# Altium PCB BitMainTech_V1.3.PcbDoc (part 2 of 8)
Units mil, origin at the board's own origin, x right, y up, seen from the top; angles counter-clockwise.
Board outline 9842.52 x 6082.68 mil, 4 copper layers (Top Layer, Mid-Layer 1, Mid-Layer 2, Bottom Layer); 987 components, 282 nets, 3694 pads, 3174 vias.
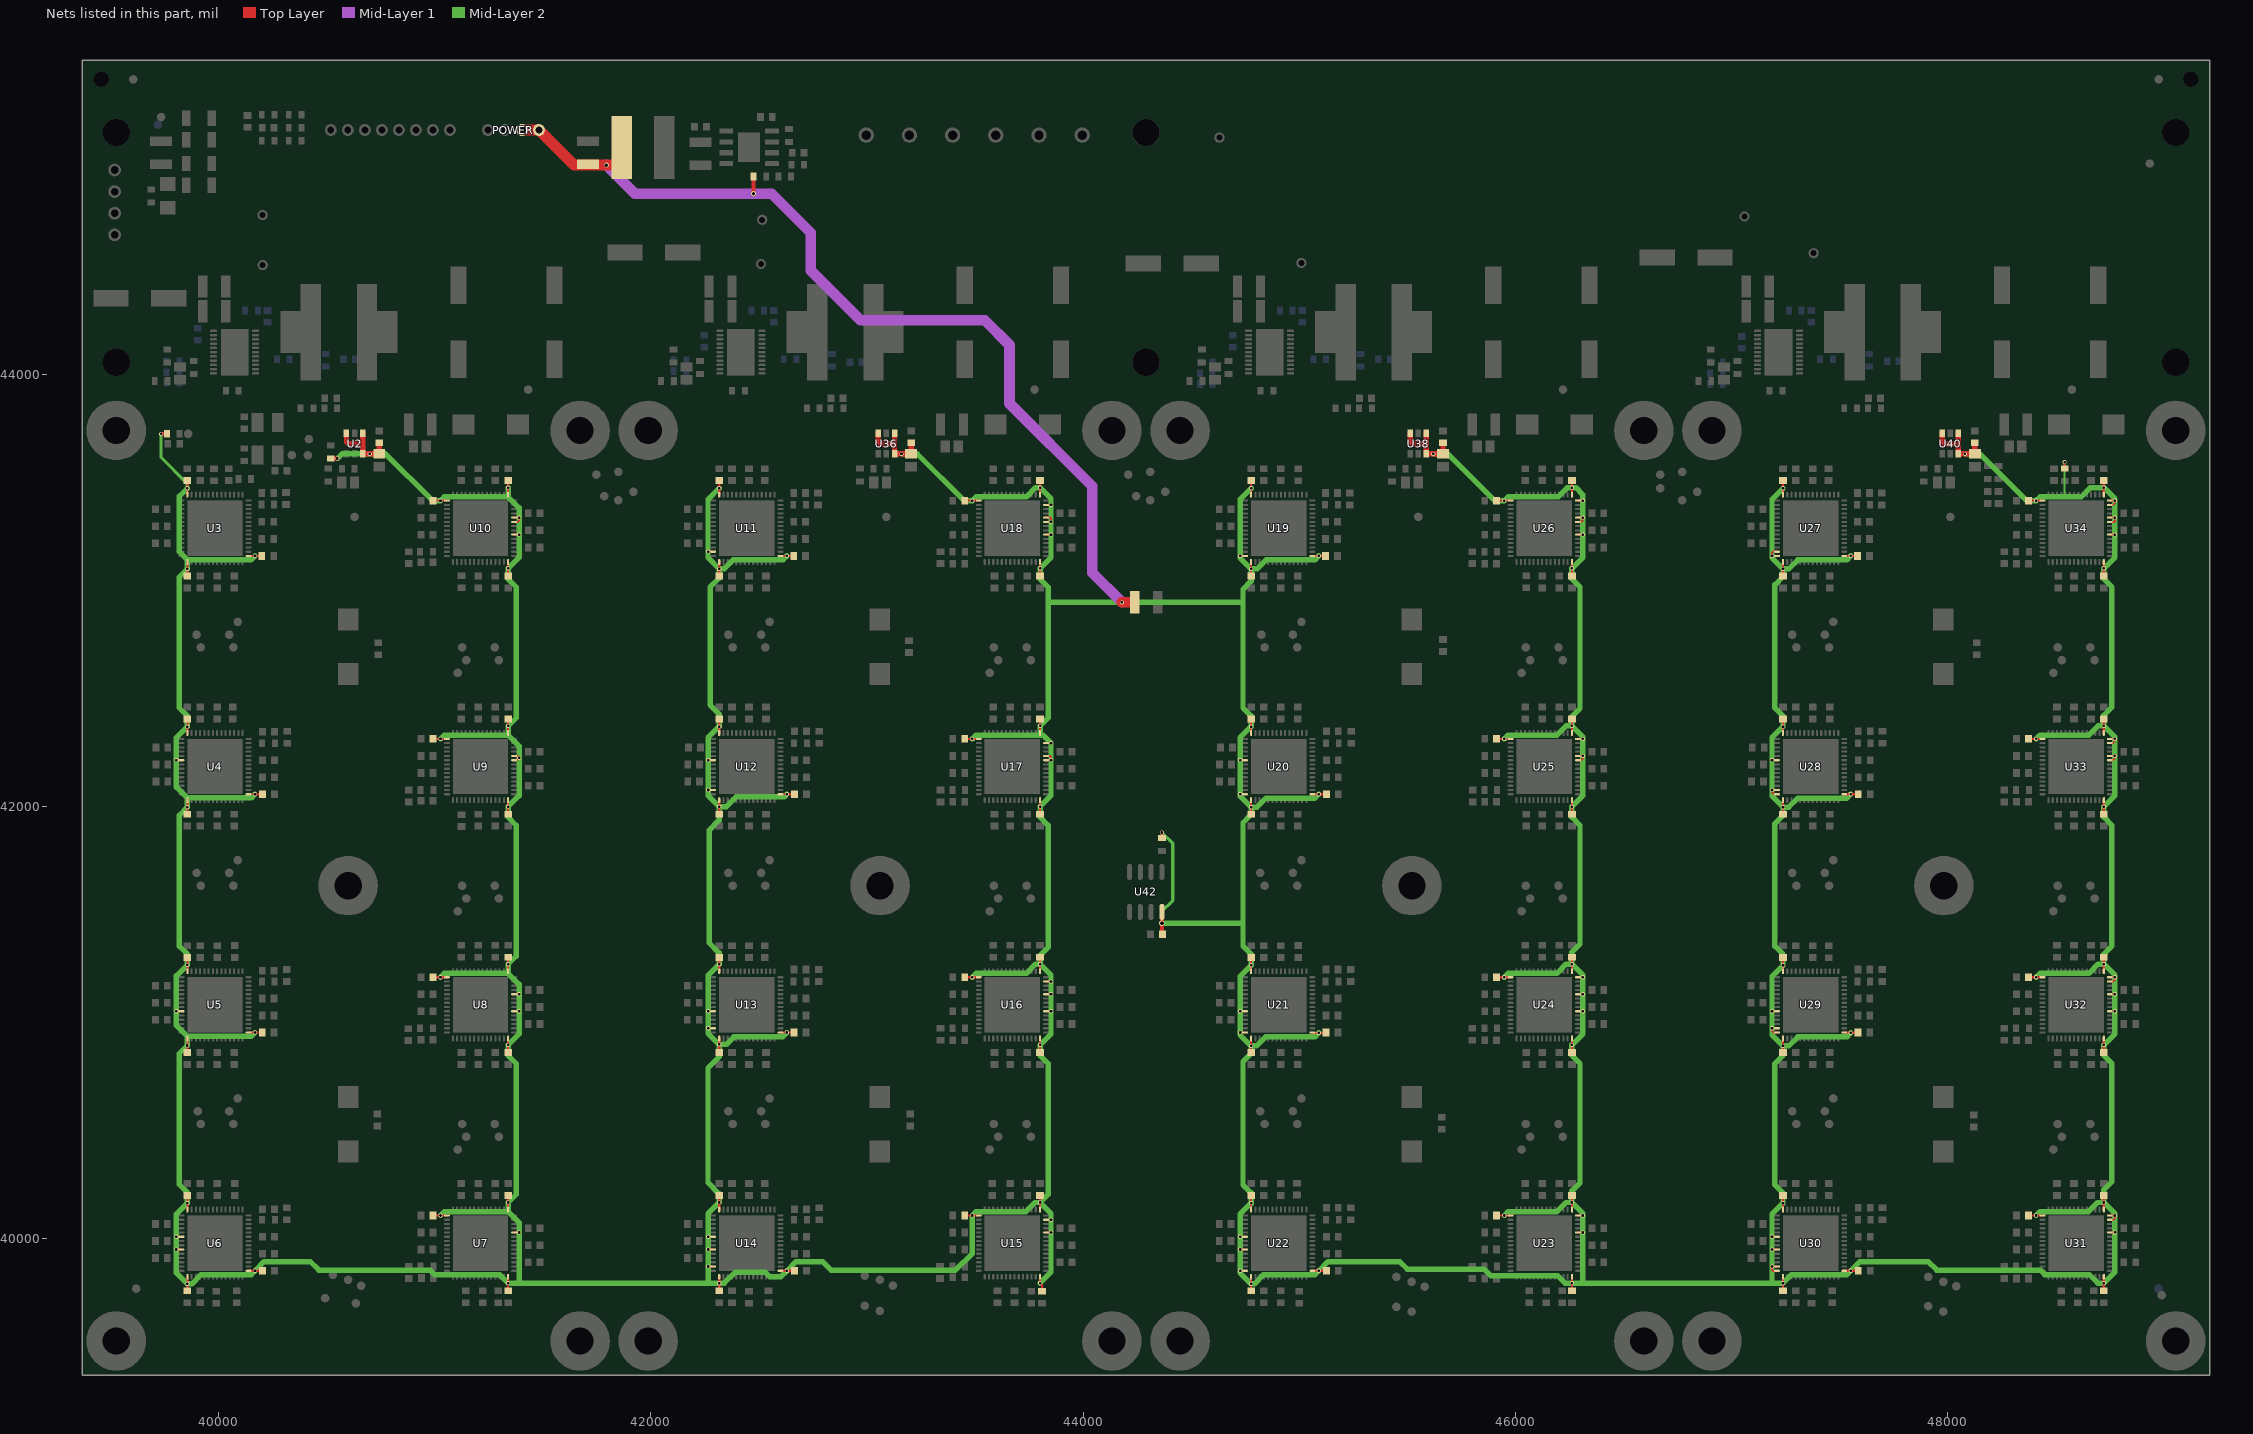
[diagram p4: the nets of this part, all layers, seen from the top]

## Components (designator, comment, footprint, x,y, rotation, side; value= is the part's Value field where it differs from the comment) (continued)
TP69 "TP" TP_SMD 44245.63,43436.63 r90 top
TP70 "TP" TP_SMD 43738.94,40531.5 r90 top
TP71 "TP" TP_SMD 43738.94,41633.86 r90 top
TP72 "TP" TP_SMD 43738.94,42736.22 r0 top
TP73 "TP" TP_SMD 44311.02,43547.99 r90 top
TP74 "TP" TP_SMD 44380.63,43456.13 r90 top
TP75 "TP" TP_SMD 43587.83,40531.5 r90 top
TP76 "TP" TP_SMD 43607.52,40472.44 r90 top
TP77 "TP" TP_SMD 43587.83,41633.86 r90 top
TP78 "TP" TP_SMD 43607.52,41574.8 r90 top
TP79 "TP" TP_SMD 43587.83,42736.22 r0 top
TP80 "TP" TP_SMD 43607.52,42677.17 r90 top
TP81 "TP" TP_SMD 44310.63,43417.13 r90 top
TP82 "TP" TP_SMD 44209.45,43536 r90 top
TP83 "TP" TP_SMD 43758.62,40472.44 r90 top
TP84 "TP" TP_SMD 43568.15,40413.39 r90 top
TP85 "TP" TP_SMD 43758.62,41574.8 r90 top
TP86 "TP" TP_SMD 43568.15,41515.75 r90 top
TP87 "TP" TP_SMD 43758.62,42677.17 r90 top
TP88 "TP" TP_SMD 43568.15,42618.11 r90 top
TP89 "TP" TP_SMD 44839.8,42736.22 r0 top
TP90 "TP" TP_SMD 44839.8,41633.86 r90 top
TP91 "TP" TP_SMD 44839.8,40531.5 r90 top
TP92 "TP" TP_SMD 45450,39685.62 r90 top
TP93 "TP" TP_SMD 44990.91,42736.22 r0 top
TP94 "TP" TP_SMD 44971.22,42795.28 r90 top
TP95 "TP" TP_SMD 44990.91,41633.86 r0 top
TP96 "TP" TP_SMD 44971.22,41692.91 r90 top
TP97 "TP" TP_SMD 44990.91,40531.5 r90 top
TP98 "TP" TP_SMD 44971.22,40590.55 r90 top
TP99 "TP" TP_SMD 45520,39801.18 r90 top
TP100 "TP" TP_SMD 45580,39778.98 r90 top
TP101 "TP" TP_SMD 44825,42795.28 r90 top
TP102 "TP" TP_SMD 45010.59,42854.33 r90 top
TP103 "TP" TP_SMD 44820.12,41692.91 r90 top
TP104 "TP" TP_SMD 45010.59,41751.97 r90 top
TP105 "TP" TP_SMD 44820.12,40590.55 r90 top
TP106 "TP" TP_SMD 45010.59,40649.61 r90 top
TP107 "TP" TP_SMD 45520,39663.82 r90 top
TP108 "TP" TP_SMD 45450,39824.23 r90 top
TP109 "TP" TP_SMD 46199.57,40531.5 r90 top
TP110 "TP" TP_SMD 46199.57,41633.86 r90 top
TP111 "TP" TP_SMD 46199.57,42736.22 r90 top
TP112 "TP" TP_SMD 46670.08,43472.81 r90 top
TP113 "TP" TP_SMD 46048.46,40531.5 r90 top
TP114 "TP" TP_SMD 46068.15,40472.44 r90 top
TP115 "TP" TP_SMD 46048.46,41633.86 r90 top
TP116 "TP" TP_SMD 46068.15,41574.8 r90 top
TP117 "TP" TP_SMD 46048.46,42736.22 r90 top
TP118 "TP" TP_SMD 46068.15,42677.17 r90 top
TP119 "TP" TP_SMD 46771.65,43547.99 r90 top
TP120 "TP" TP_SMD 46841.26,43456.13 r90 top
TP121 "TP" TP_SMD 46219.25,40472.44 r90 top
TP122 "TP" TP_SMD 46028.78,40413.39 r90 top
TP123 "TP" TP_SMD 46219.25,41574.8 r90 top
TP124 "TP" TP_SMD 46028.78,41515.75 r90 top
TP125 "TP" TP_SMD 46219.25,42677.17 r90 top
TP126 "TP" TP_SMD 46028.78,42618.11 r90 top
TP127 "TP" TP_SMD 46771.26,43417.13 r90 top
TP128 "TP" TP_SMD 46670.08,43536 r90 top
TP129 "VPLL" TP_SMD_1.0 43090.55,43340 r0 top
TP130 "TP" TP_SMD 47300.43,41633.86 r90 top
TP131 "TP" TP_SMD 47300.43,40531.5 r90 top
TP132 "TP" TP_SMD 47910,39688.82 r90 top
TP133 "TP" TP_SMD 47451.54,42736.22 r0 top
TP134 "TP" TP_SMD 47431.85,42795.28 r90 top
TP135 "TP" TP_SMD 47451.54,41633.86 r0 top
TP136 "TP" TP_SMD 47431.85,41692.91 r90 top
TP137 "TP" TP_SMD 47451.54,40531.5 r90 top
TP138 "TP" TP_SMD 47431.85,40590.55 r90 top
TP139 "TP" TP_SMD 47980,39801.18 r90 top
TP140 "TP" TP_SMD 48040,39781.18 r90 top
TP141 "TP" TP_SMD 47280.75,42795.28 r90 top
TP142 "TP" TP_SMD 47471.22,42854.33 r90 top
TP143 "TP" TP_SMD 47280.75,41692.91 r90 top
TP144 "TP" TP_SMD 47471.22,41751.97 r90 top
TP145 "TP" TP_SMD 47280.75,40590.55 r90 top
TP146 "TP" TP_SMD 47471.22,40649.61 r90 top
TP147 "TP" TP_SMD 47980,39663.82 r90 top
TP148 "TP" TP_SMD 47910,39824.23 r90 top
TP149 "TP" TP_SMD 48660.2,40531.5 r90 top
TP150 "TP" TP_SMD 48660.2,41633.86 r90 top
TP151 "TP" TP_SMD 48660.2,42736.22 r90 top
TP152 "TP" TP_SMD 48509.09,40531.5 r90 top
TP153 "TP" TP_SMD 48528.78,40472.44 r90 top
TP154 "TP" TP_SMD 48509.09,41633.86 r90 top
TP155 "TP" TP_SMD 48528.78,41574.8 r90 top
TP156 "TP" TP_SMD 48509.09,42736.22 r90 top
TP157 "TP" TP_SMD 48528.78,42677.17 r90 top
TP158 "TP" TP_SMD 48679.88,40472.44 r90 top
TP159 "TP" TP_SMD 48489.41,40413.39 r90 top
TP160 "TP" TP_SMD 48679.88,41574.8 r90 top
TP161 "TP" TP_SMD 48489.41,41515.75 r90 top
TP162 "TP" TP_SMD 48679.88,42677.17 r90 top
TP163 "TP" TP_SMD 48489.41,42618.11 r90 top
TP164 "VOUT" TP_SMD_1.0 43775.59,43929.13 r0 top
TP165 "+12V" TP 42515.75,44714.57 r0 top
TP166 "GND" TP 42510,44510 r0 top
TP167 "VPLL" TP_SMD_1.0 40629.92,43340 r90 top
TP168 "VOUT" TP_SMD_1.0 46220.47,43929.13 r0 top
TP169 "+12V" TP 44630.91,45094.49 r0 top
TP170 "GND" TP 45010,44515 r0 top
TP171 "VPLL" TP_SMD_1.0 45551.18,43340 r0 top
TP172 "VOUT" TP_SMD_1.0 48574.8,43929.13 r0 top
TP173 "+12V" TP 47060,44730 r0 top
TP174 "GND" TP 47380,44560 r0 top
TP175 "VPLL" TP_SMD_1.0 48011.81,43340 r0 top
U1 "TPS53355DQPR" TPS53355 40171.26,44003.94 r180 top locked
U2 "RT9041B-10GE" SOT23-6_L 40629.92,43679.13 r270 top
U3 "BM1380" QFN56 39984.25,43287.4 r270 top locked
U4 "BM1380" QFN56 39984.25,42185.04 r270 top locked
U5 "BM1380" QFN56 39984.25,41082.68 r270 top locked
U6 "BM1380" QFN56 39984.25,39980.32 r270 top locked
U7 "BM1380" QFN56 41212.6,39980.32 r90 top locked
U8 "BM1380" QFN56 41212.6,41082.68 r90 top locked
U9 "BM1380" QFN56 41212.6,42185.04 r90 top locked
U10 "BM1380" QFN56 41212.6,43287.4 r90 top locked
U11 "BM1380" QFN56 42444.88,43287.4 r270 top locked
U12 "BM1380" QFN56 42444.88,42185.04 r270 top locked
U13 "BM1380" QFN56 42444.88,41082.68 r270 top
U14 "BM1380" QFN56 42444.88,39980.31 r270 top locked
U15 "BM1380" QFN56 43673.23,39980.32 r90 top locked
U16 "BM1380" QFN56 43673.23,41082.68 r90 top locked
U17 "BM1380" QFN56 43673.23,42185.04 r90 top locked
U18 "BM1380" QFN56 43673.23,43287.4 r90 top locked
U19 "BM1380" QFN56 44905.51,43287.4 r270 top locked
U20 "BM1380" QFN56 44905.51,42185.04 r270 top locked
U21 "BM1380" QFN56 44905.51,41082.68 r270 top locked
U22 "BM1380" QFN56 44905.51,39980.32 r270 top locked
U23 "BM1380" QFN56 46133.86,39980.32 r90 top locked
U24 "BM1380" QFN56 46133.86,41082.68 r90 top locked
U25 "BM1380" QFN56 46133.86,42185.04 r90 top locked
U26 "BM1380" QFN56 46133.86,43287.4 r90 top locked
U27 "BM1380" QFN56 47366.14,43287.4 r270 top locked
U28 "BM1380" QFN56 47366.14,42185.04 r270 top locked
U29 "BM1380" QFN56 47366.14,41082.68 r270 top locked
U30 "BM1380" QFN56 47366.14,39980.32 r270 top locked
U31 "BM1380" QFN56 48594.49,39980.32 r90 top locked
U32 "BM1380" QFN56 48594.49,41082.68 r90 top locked
U33 "BM1380" QFN56 48594.49,42185.04 r90 top locked
U34 "BM1380" QFN56 48594.49,43287.4 r90 top locked
U35 "MP1484" SOIC8L 42455,45050 r270 top
U36 "RT9041B-10GE" SOT23-6_L 43090.55,43679.13 r270 top
U37 "TPS53355DQPR" TPS53355 44959.45,44003.94 r180 top
U38 "RT9041B-10GE" SOT23-6_L 45551.18,43679.13 r270 top
U39 "TPS53355DQPR" TPS53355 47313.78,44003.94 r180 top
U40 "RT9041B-10GE" SOT23-6_L 48011.81,43679.13 r270 top
U41 "TPS53355DQPR" TPS53355 42513.78,44003.94 r180 top
U42 "LM75A" SO8_L 44290,41605 r270 top locked
Y1 "25MHz" SMX2 40228.35,43702.76 r90 top
? "ANT_Logo" ANT_Logo_930x370 48085,44935 r0 top

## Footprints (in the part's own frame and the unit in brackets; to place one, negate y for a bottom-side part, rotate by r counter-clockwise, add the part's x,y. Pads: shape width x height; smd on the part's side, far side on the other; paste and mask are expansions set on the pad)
4Pin_180 [mm]
  round 1.4 hole 0.8: 1(-3,0) 2(-1,0) 3(1,0) 4(3,0)
  silkscreen extent -4.8,-2.5 4.8,2.9
4PINFAN [mm]
  round 1.5 hole 0.9 paste+0.05 mask+0.05: 1(3.81,0) 2(1.27,0) 3(-1.27,0) 4(-3.81,0)
  silkscreen extent -5.03,-2.85 5,2.85
8Pin_180 [mm]
  round 1.4 hole 0.8: 1(-7,0) 2(-5,0) 3(-3,0) 4(-1,0) 5(1,0) 6(3,0) 7(5,0) 8(7,0)
  silkscreen extent -8.8,-2.5 8.8,2.9
ANT_Logo_930x370 [mil]
  silkscreen extent -435,-69 481,283
CAP1210(3225)_TAN [mm] "Chip Capacitor, Body 3.2x2.5mm, IPC High Density"
  rect 1.1x2.6 smd: 1(-1.35,0) 2(1.35,0)
  silkscreen extent -0.4,-1.2 0.42,1.2, body extent -1.7,-1.35 1.7,1.35, height 1.35
CAPC2012L [mm] "Chip Capacitor, Body 2.0x1.3mm, IPC High Density"
  rect 1.1x1.4 smd: 1(-0.75,0) 2(0.75,0)
  silkscreen extent -1.6,-0.6 -1.6,0.6, body extent -1.1,-0.72 1.1,0.72, height 1.1
CAPC3225L [mm] "Chip Capacitor, Body 3.2x2.5mm, IPC High Density"
  rect 1.1x2.6 smd: 1(1.35,0) 2(-1.35,0)
  silkscreen extent -0.4,-1.2 0.4,1.2, body extent -1.7,-1.35 1.7,1.35, height 1.35
CC0603(1608) [mm] "Chip Capacitor, Body 1.6x0.8mm, IPC High Density"
  rect 0.8x0.9 smd: 1(-0.7,0) 2(0.7,0)
  silkscreen extent -1.4,-0.35 -1.4,0.35, body extent -0.87,-0.48 0.87,0.47, height 0.85
CC0805(2012) [mm] "Chip Capacitor, Body 2.0x1.3mm, IPC High Density"
  rect 1.1x1.4 smd: 1(-0.75,0) 2(0.75,0)
  silkscreen extent -1.6,-0.6 -1.6,0.6, body extent -1.1,-0.73 1.1,0.72, height 1.1
CC1210(3225) [mm] "Chip Capacitor, Body 3.2x2.5mm, IPC High Density"
  rect 1.1x2.6 smd: 1(1.35,0) 2(-1.35,0)
  silkscreen extent -0.4,-1.2 0.42,1.2, body extent -1.7,-1.35 1.7,1.35, height 1.35
CD3216-1206 [mm] "Chip Diode; Body 3.2 x 1.6 mm (LxW typ)"
  rect 1.6x1.8 smd: 1(-1.4,0) 2(1.4,0)
  silkscreen extent -0.3,-0.8 0.3,0.8
D [mm] "Capacitor, SM Tantalum; Body 7.3 x 4.3 mm (LxW typ)"
  rect 2.6x2.4 smd: 1(-3.2,0) 2(3.2,0)
  silkscreen extent -4.57,-2.3 3.8,2.42
E12 [mm] "SVP"
  rect 1.9x4.15 smd: 1(0,-3.4) 2(0,3.4)
  silkscreen extent -4.31,-5.71 4.2,5.71, body extent -3.98,-3.99 4,3.99, height 12.8
F12 [mm] "SVP"
  rect 1.9x4.4 smd: 1(0,-4.35) 2(0,4.35)
  silkscreen extent -5.2,-6.84 5.2,6.85, body extent -5,-5.29 5.01,5.28, height 13.4
FB0603(1608) [mm] "Ferrite Bead"
  rect 0.7x0.9 smd: 1(0,0) 2(1.5,0)
  silkscreen extent 0.55,-0.35 0.95,0.35, body extent -0.1,-0.48 1.6,0.47, height 0.6
HOLE_3.2#1 [mm]
  round 3.2 hole 3.2 unplated: 0(0,10)
HOLE_3.2#2 [mm]
  round 3.2 hole 3.2 unplated: 0(0,0)
IHLP5050 [mm]
  rect 2.945x4.95 smd: 1(-5.407,0) 2(5.407,0)
  rect 2.388x11.328 smd: 1(-3.28,0) 2(3.32,-0.03)
  silkscreen extent -7.14,-6.45 7.14,6.45, body extent -6.6,-6.45 6.6,6.45, height 6.5
INDC3216L [mm] "Chip Inductor, Body 3.2x1.6mm, IPC High Density"
  rect 1x1.8 smd: 1(-1.5,0) 2(1.5,0)
  silkscreen extent -0.6,-0.8 0.6,0.8, body extent -1.75,-0.95 1.75,0.95, height 1.9
LED0603(1608) [mm] "Chip LED, Body 1.6x0.8mm, IPC High Density"
  rect 0.8x0.9 smd: 1(0.7,0) 2(-0.7,0)
  silkscreen extent -1.4,-0.35 -1.4,0.35, body extent -0.87,-0.48 0.87,0.47, height 0.85
MASK [mm] "SMD MASK 1mm"
  round 1 smd: 0(0,0)
  Top Layer circle w0.254: c0,0 r1
MHOLE2 [mm]
  round 7 hole 3.2 unplated: 0(0,0)
QFN56 [mm]
  oval 0.7x0.25 smd: 1(-3.95,3.25) 2(-3.95,2.75) 3(-3.95,2.25) 4(-3.95,1.75) 5(-3.95,1.25) 6(-3.95,0.75) 7(-3.95,0.25) 8(-3.95,-0.25) 9(-3.95,-0.75) 10(-3.95,-1.25) 11(-3.95,-1.75) 12(-3.95,-2.25) 13(-3.95,-2.75) 14(-3.95,-3.25) 29(3.95,-3.25) 30(3.95,-2.75) 31(3.95,-2.25) 32(3.95,-1.75) 33(3.95,-1.25) 34(3.95,-0.75) 35(3.95,-0.25) 36(3.95,0.25) 37(3.95,0.75) 38(3.95,1.25) 39(3.95,1.75) 40(3.95,2.25) 41(3.95,2.75) 42(3.95,3.25)
  oval 0.25x0.7 smd: 15(-3.25,-3.95) 16(-2.75,-3.95) 17(-2.25,-3.95) 18(-1.75,-3.95) 19(-1.25,-3.95) 20(-0.75,-3.95) 21(-0.25,-3.95) 22(0.25,-3.95) 23(0.75,-3.95) 24(1.25,-3.95) 25(1.75,-3.95) 26(2.25,-3.95) 27(2.75,-3.95) 28(3.25,-3.95) 43(3.25,3.95) 44(2.75,3.95) 45(2.25,3.95) 46(1.75,3.95) 47(1.25,3.95) 48(0.75,3.95) 49(0.25,3.95) 50(-0.25,3.95) 51(-0.75,3.95) 52(-1.25,3.95) 53(-1.75,3.95) 54(-2.25,3.95) 55(-2.75,3.95) 56(-3.25,3.95)
  rect 6.5x6.5 smd: 57(0,0)
  rect 6.5x6.5 smd far side: 57(0,0)
  silkscreen extent -4.9,-4.23 4.23,4.23, body extent -4.08,-4.08 4.08,4.08, height 0.9
RR0603(1608) [mm] "Chip Resistor, Body 1.6x0.8mm, IPC High Density"
  rect 0.7x0.9 smd: 1(-0.75,0) 2(0.75,0)
  silkscreen extent -0.2,-0.35 0.2,0.35, body extent -0.85,-0.48 0.85,0.47, height 0.6
SMD_L_7.4x7.4 [mm]
  rect 2.4x7.4 smd: 1(-2.5,0) 2(2.5,0)
  silkscreen extent -3.8,-4 3.8,4
SMX2 [mm]
  rect 2.2x1.4 smd: 1(-1.925,-1.175) 2(1.875,-1.175) 3(1.875,1.225) 4(-1.925,1.225)
  silkscreen extent -2.99,-2.51 2.47,1.68
SO8_L [mm] "SOIC, 8-Leads, Body 4.9x3.9mm, Pitch 1.27mm, IPC High Density"
  oval 1.9x0.6 smd: 1(-2.35,1.905) 2(-2.35,0.635) 3(-2.35,-0.635) 4(-2.35,-1.905) 5(2.35,-1.905) 6(2.35,-0.635) 7(2.35,0.635) 8(2.35,1.905)
  silkscreen extent -2.47,-2.5 1,2.88, body extent -2,-2.5 2,2.5, height 1.75
SOIC8L [mm]
  rect 3.51x2.62 smd: 0(0,0)
  rect 0.61x1.6 smd: 1(-1.905,-2.7) 2(-0.635,-2.7) 3(0.635,-2.7) 4(1.905,-2.7) 5(1.905,2.7) 6(0.635,2.7) 7(-0.635,2.7) 8(-1.905,2.7)
  silkscreen extent -2.4,-2 2.4,2
SOT23-6_L [mm] "SOT23, 6-Leads, Body 2.9x1.6mm, Pitch 0.95mm, Lead Span 2.7mm, IPC High Density"
  rect 0.9x0.65 smd: 1(-1.2,0.95) 2(-1.2,0) 3(-1.2,-0.95) 4(1.2,-0.95) 5(1.2,0) 6(1.2,0.95)
  silkscreen extent -1.32,-1.55 0.35,1.95, body extent -0.9,-1.55 0.9,1.55, height 1.45
TERMINAL_3 [mm]
  round 1.8 hole 1.1: 1(0,0) 2(5.08,0) 3(10.16,0)
  silkscreen extent -2.54,-3.81 12.7,3.81
TP [mm]
  round 1.2 hole 0.7: 1(0,0)
  silkscreen extent -1.27,-1.27 1.27,1.27
TP_SMD [mm]
  round 1 smd: 1(0,0)
TP_SMD_1.0 [mm]
  round 1 smd: 1(0,0)
  silkscreen extent -1,-1 1,1
TPS53355 [mm]
  oval 0.85x0.28 smd: 1(-0.02,0) 2(-0.02,-0.5) 3(-0.02,-1) 4(-0.02,-1.5) 5(-0.02,-2) 6(-0.02,-2.5) 7(-0.02,-3) 8(-0.02,-3.5) 9(-0.02,-4) 10(-0.02,-4.5) 11(-0.02,-5) 12(4.92,-5) 13(4.92,-4.5) 14(4.92,-4) 15(4.92,-3.5) 16(4.92,-3) 17(4.92,-2.5) 18(4.92,-2) 19(4.92,-1.5) 20(4.92,-1) 21(4.92,-0.5) 22(4.92,0)
  rect 3.24x5.48 smd: PG(2.45,-2.5)
  rect 3.24x5.48 smd far side: PG(2.45,-2.5)
  silkscreen extent -0.8,-5.55 5,0.55

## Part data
C1 C5 C6 C7 C10 C11 C12 C13 C21 C22 C23 C24 C25 C26 C27 C28 C29 C30 C31 C32 C33 C34 C35 C36 C37 C38 C39 C40 C41 C42 C43 C44 C45 C46 C47 C48 C49 C50 C51 C52 C53 C54 C55 C56 C57 C58 C59 C60 C61 C62 C63 C64 C65 C66 C67 C68 C69 C70 C71 C72 C73 C74 C75 C76 C77 C78 C79 C80 C81 C82 C83 C84 C85 C86 C87 C88 C89 C90 C91 C92 C93 C94 C95 C96 C97 C98 C99 C100 C101 C102 C103 C104 C105 C106 C107 C108 C109 C110 C111 C112 C113 C114 C115 C116 C117 C118 C119 C120 C121 C122 C123 C124 C125 C126 C127 C128 C129 C130 C131 C132 C133 C134 C135 C136 C137 C138 C139 C140 C141 C142 C143 C144 C145 C146 C147 C148 C149 C150 C151 C156 C157 C158 C159 C160 C161 C162 C163 C164 C165 C166 C167 C168 C169 C170 C171 C172 C173 C174 C175 C176 C177 C178 C179 C180 C181 C182 C183 C184 C185 C186 C187 C188 C189 C190 C191 C192 C193 C194 C195 C196 C197 C198 C199 C200 C201 C202 C203 C204 C205 C206 C207 C208 C209 C210 C211 C212 C213 C214 C215 C216 C217 C218 C219 C220 C221 C222 C223 C224 C225 C226 C227 C228 C229 C230 C231 C232 C233 C234 C235 C236 C237 C238 C239 C240 C241 C242 C243 C244 C245 C246 C247 C248 C249 C250 C251 C252 C253 C254 C255 C256 C257 C258 C259 C260 C261 C262 C263 C264 C265 C266 C267 C268 C269 C270 C271 C272 C273 C274 C275 C276 C277 C278 C279 C280 C281 C282 C283 C288 C289 C290 C291 C292 C293 C294 C295 C296 C297 C298 C299 C300 C301 C302 C303 C304 C305 C306 C307 C308 C309 C310 C311 C312 C313 C314 C315 C316 C317 C318 C319 C320 C321 C322 C323 C324 C325 C326 C327 C328 C329 C330 C331 C332 C333 C334 C335 C336 C337 C338 C339 C340 C341 C342 C343 C344 C345 C346 C347 C348 C349 C350 C351 C352 C353 C354 C355 C356 C357 C358 C359 C360 C361 C362 C363 C364 C365 C366 C367 C368 C369 C370 C371 C372 C373 C374 C375 C376 C377 C378 C379 C380 C381 C382 C383 C384 C385 C386 C387 C388 C389 C390 C391 C392 C393 C394 C395 C396 C397 C398 C399 C400 C401 C402 C403 C404 C405 C406 C407 C408 C409 C410 C411 C412 C413 C414 C415 C420 C421 C422 C423 C424 C425 C426 C427 C428 C429 C430 C431 C432 C433 C434 C435 C436 C437 C438 C439 C440 C441 C442 C443 C444 C445 C446 C447 C448 C449 C450 C451 C452 C453 C454 C455 C456 C457 C458 C459 C460 C461 C462 C463 C464 C465 C466 C467 C468 C469 C470 C471 C472 C473 C474 C475 C476 C477 C478 C479 C480 C481 C482 C483 C484 C485 C486 C487 C488 C489 C490 C491 C492 C493 C494 C495 C496 C497 C498 C499 C500 C501 C502 C503 C504 C505 C506 C507 C508 C509 C510 C511 C512 C513 C514 C515 C516 C517 C518 C519 C520 C521 C522 C523 C524 C525 C526 C527 C528 C529 C530 C531 C532 C533 C534 C535 C536 C537 C538 C539 C540 C541 C542 C543 C544 C545 C546 C547 C553 C554 C557 C558 C559 C560 C564 C568 C569 C570 C573 C574 C575 C576 C580 C584 C585 C586 C589 C590 C591 C592 C598 C600: library part Cap, "Capacitor"
C2 C3 C565 C566 C581 C582 C596 C597 C606 C607 C608 C609: library part "Cap Pol2", "Polarized Capacitor (SMD)"
C4 C567 C583 C599: library part "Cap Pol3", "Polarized Capacitor (Surface Mount)"
C8 C9 C14 C15 C16 C19 C20 C154 C155 C286 C287 C418 C419 C548 C549 C550 C551 C552 C555 C556 C561 C562 C563 C571 C572 C577 C578 C579 C587 C588 C593 C594 C595 C601 C602 C603 C604 C605: library part "Cap Semi", "Capacitor (Semiconductor SIM Model)"
C17 C18 C152 C153 C284 C285 C416 C417: library part T492C, "Solid Tantalum Chip Capacitor, T492 Series - CWR11 Style Per Mil-PRF-55365/8"
D1: "High Conductance Fast Diode"
FAN1 POWER: "Header, 4-Pin"
FB1 FB2 FB3 FB4 FB5 FB6 FB7 FB8 FB9 FB10 FB11 FB12 FB13 FB14 FB15 FB16 FB17 FB18 FB19 FB20 FB21 FB22 FB23 FB24 FB25 FB26 FB27 FB28 FB29 FB30 FB31 FB32: library part FB, "Inductor"
FB33 FB34 FB35 FB36: library part Res3, "Resistor"
J1: library part "Header 8", "Header, 8-Pin"
L1 L2 L3 L4 L5: library part Inductor, "Inductor"
M1 M2 M3 M4 M5 M6 M7 M8 M9 M10 M11 M12 M13 M14 M15 M16 M17 M18 M19 M20 M21 M22 M23 M27 M28 M32: library part M_Hole
P1 P2: library part "Header 3", "Header, 3-Pin"
R1 R2 R3 R4 R5 R6 R7 R8 R9 R10 R11 R12 R13 R14 R15 R16 R17 R18 R19 R20 R21 R22 R23 R24 R25 R26 R27 R28 R29 R30 R31 R32 R33 R34 R35 R36 R37 R38 R39 R40 R41 R42 R43 R44 R45 R46 R47 R48 R49 R50 R51 R52 R53 R54 R55 R56 R57 R58 R59 R60 R61 R62 R63 R64 R65 R66 R67 R68 R69 R70 R71 R72 R73 R74: library part Res1, "Resistor"
RF TF: library part LED0, "Typical INFRARED GaAs LED"
TP1 TP129 TP164 TP167 TP168 TP171 TP172 TP175: library part TP, "Test Point"
TP2 TP3 TP165 TP166 TP169 TP170 TP173 TP174: library part TP
TP4 TP5 TP6 TP7 TP8 TP9 TP10 TP11 TP12 TP13 TP14 TP15 TP16 TP17 TP18 TP19 TP20 TP21 TP22 TP23 TP24 TP25 TP26 TP27 TP28 TP29 TP30 TP31 TP32 TP33 TP34 TP35 TP36 TP37 TP38 TP39 TP40 TP41 TP42 TP43 TP44 TP45 TP46 TP47 TP48 TP49 TP50 TP51 TP52 TP53 TP54 TP55 TP56 TP57 TP58 TP59 TP60 TP61 TP62 TP63 TP64 TP65 TP66 TP67 TP68 TP69 TP70 TP71 TP72 TP73 TP74 TP75 TP76 TP77 TP78 TP79 TP80 TP81 TP82 TP83 TP84 TP85 TP86 TP87 TP88 TP89 TP90 TP91 TP92 TP93 TP94 TP95 TP96 TP97 TP98 TP99 TP100 TP101 TP102 TP103 TP104 TP105 TP106 TP107 TP108 TP109 TP110 TP111 TP112 TP113 TP114 TP115 TP116 TP117 TP118 TP119 TP120 TP121 TP122 TP123 TP124 TP125 TP126 TP127 TP128 TP130 TP131 TP132 TP133 TP134 TP135 TP136 TP137 TP138 TP139 TP140 TP141 TP142 TP143 TP144 TP145 TP146 TP147 TP148 TP149 TP150 TP151 TP152 TP153 TP154 TP155 TP156 TP157 TP158 TP159 TP160 TP161 TP162 TP163: "Test Point"
U1: library part TPS53355, "TI DC-DC,Output 30A."
U37 U39 U41: library part TPS53355
U42: "NXP Digital temperature sensor and thermal watchdog"
Y1: library part XTAL, "Crystal Oscillator"

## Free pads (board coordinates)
  round 70.87 hole 70.87 unplated: ""(39458.66,45364.17) ""(49124.02,45364.17)

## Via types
v1: diameter 19, hole 12, Top Layer to Bottom Layer, 1347 vias
v2: diameter 25.98, hole 12.99, Top Layer to Bottom Layer, 800 vias
v3: diameter 24, hole 16, Top Layer to Bottom Layer, 778 vias
v4: diameter 50, hole 28, Top Layer to Bottom Layer, 160 vias
v5: diameter 19.68, hole 11.81, Top Layer to Bottom Layer, 84 vias
v6: diameter 26, hole 18, Top Layer to Bottom Layer, 5 vias

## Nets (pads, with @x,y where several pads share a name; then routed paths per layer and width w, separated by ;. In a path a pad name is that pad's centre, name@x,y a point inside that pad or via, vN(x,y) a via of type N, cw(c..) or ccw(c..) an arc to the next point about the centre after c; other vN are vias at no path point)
+3.3V: C14.2 C15.2 C32.2 C33.2 C34.2 C35.2 C36.2 C37.2 C38.2 C39.2 C40.2 C41.2 C42.2 C43.2 C96.2 C97.2 C98.2 C99.2 C100.2 C101.2 C102.2 C103.2 C104.2 C105.2 C106.2 C107.2 C164.2 C165.2 C166.2 C167.2 C168.2 C169.2 C170.2 C171.2 C172.2 C173.2 C174.2 C175.2 C228.2 C229.2 C230.2 C231.2 C232.2 C233.2 C234.2 C235.2 C236.2 C237.2 C238.2 C239.2 C296.2 C297.2 C298.2 C299.2 C300.2 C301.2 C302.2 C303.2 C304.2 C305.2 C306.2 C307.2 C360.2 C361.2 C362.2 C363.2 C364.2 C365.2 C366.2 C367.2 C368.2 C369.2 C370.2 C371.2 C428.2 C429.2 C430.2 C431.2 C432.2 C433.2 C434.2 C435.2 C436.2 C437.2 C438.2 C439.2 C492.2 C493.2 C494.2 C495.2 C496.2 C497.2 C498.2 C499.2 C500.2 C501.2 C502.2 C503.2 C550.2 C561.2 C562.2 C577.2 C578.2 C593.2 C594.2 C601.1 C602.2 L5.2 POWER.3 POWER.4 R15.1 R18.2 R21.2 R71.1 R74.2 U2.1 U2.3 U2.6 U3.14 U3.29 U3.43 U4.14 U4.20 U4.29 U4.43 U5.14 U5.23 U5.29 U5.43 U6.14 U6.20 U6.23 U6.29 U6.43 U7.14 U7.24 U7.29 U7.43 U8.14 U8.20 U8.24 U8.29 U8.43 U9.14 U9.23 U9.24 U9.29 U9.43 U10.14 U10.20 U10.23 U10.24 U10.29 U10.43 U11.14 U11.27 U11.29 U11.43 U12.14 U12.20 U12.27 U12.29 U12.43 U13.14 U13.23 U13.27 U13.29 U13.43 U14.14 U14.20 U14.23 U14.27 U14.29 U14.43 U15.14 U15.24 U15.27 U15.29 U15.43 U16.14 U16.20 U16.24 U16.27 U16.29 U16.43 U17.14 U17.23 U17.24 U17.27 U17.29 U17.43 U18.14 U18.20 U18.23 U18.24 U18.27 U18.29 U18.43 U19.14 U19.28 U19.29 U19.43 U20.14 U20.20 U20.28 U20.29 U20.43 U21.14 U21.23 U21.28 U21.29 U21.43 U22.14 U22.20 U22.23 U22.28 U22.29 U22.43 U23.14 U23.24 U23.28 U23.29 U23.43 U24.14 U24.20 U24.24 U24.28 U24.29 U24.43 U25.14 U25.23 U25.24 U25.28 U25.29 U25.43 U26.14 U26.20 U26.23 U26.24 U26.28 U26.29 U26.43 U27.14 U27.27 U27.28 U27.29 U27.43 U28.14 U28.20 U28.27 U28.28 U28.29 U28.43 U29.14 U29.23 U29.27 U29.28 U29.29 U29.43 U30.14 U30.20 U30.23 U30.27 U30.28 U30.29 U30.43 U31.14 U31.24 U31.27 U31.28 U31.29 U31.43 U32.14 U32.20 U32.24 U32.27 U32.28 U32.29 U32.43 U33.14 U33.23 U33.24 U33.27 U33.28 U33.29 U33.43 U34.14 U34.20 U34.23 U34.24 U34.27 U34.28 U34.29 U34.43 U36.1 U36.3 U36.6 U38.1 U38.3 U38.6 U40.1 U40.3 U40.6 U42.8 | length 67165
  Top Layer w8: v1(43801.18,39795.28) 43810,39786.46 C168.2@43810,39757.56
  Top Layer w9: v1(39805.43,39950.79) U6.23@39828.74,39950.79 ; v1(39805.43,40009.84) U6.20@39828.74,40009.84 ; v1(39805.43,41053.15) U5.23@39828.74,41053.15 ; v1(39805.43,42214.57) U4.20@39828.74,42214.57 ; U5.43@40139.76,40954.72 v1(40169.29,40954.72) ; U4.43@40139.76,42057.09 v1(40169.29,42057.09) ; U3.43@40139.76,43159.45 v1(40169.29,43159.45) ; U7.24@41368.11,40029.53 v1(41391.42,40029.53) ; U8.20@41368.11,41053.15 v1(41391.42,41053.15) ; U8.24@41368.11,41131.89 v1(41391.42,41131.89) ; U9.23@41368.11,42214.57 41380.98,42214.57 v1(41391.42,42225) 41382.17,42234.25 U9.24@41368.11,42234.25 ; U10.20@41368.11,43257.87 v1(41391.42,43257.87) ; U10.23@41368.11,43316.93 41384.26,43316.93 41391.42,43324.08 v1(41391.42,43336.61) U10.24@41368.11,43336.61 ; v1(42266.06,39872.05) U14.27@42289.37,39872.05 ; v1(42266.06,39950.79) U14.23@42289.37,39950.79 ; v1(42266.06,40009.84) U14.20@42289.37,40009.84 ; v1(42266.06,40974.41) U13.27@42289.37,40974.41 ; v1(42266.06,41053.15) U13.23@42289.37,41053.15 ; v1(42266.06,42076.77) U12.27@42289.37,42076.77 ; v1(42266.06,42214.57) U12.20@42289.37,42214.57 ; v1(42266.06,43179.13) U11.27@42289.37,43179.13 ; U12.43@42600.39,42057.09 v1(42630,42057.09) ; U11.43@42600.39,43159.45 v1@42629.45,43159.45 ; C164.2@43452.76,40108.27 v1(43488.19,40108.27) ; U15.24@43828.74,40029.53 v1(43852.05,40029.53) ; U15.27@43828.74,40088.58 v1(43852.05,40088.58) ; U16.20@43828.74,41053.15 v1(43852.05,41053.15) ; U16.24@43828.74,41131.89 v1(43852.05,41131.89) ; U16.27@43828.74,41190.94 v1(43852.05,41190.94) ; U17.23@43828.74,42214.57 v1(43852.05,42214.57) 43852.05,42227.95 43845.75,42234.25 U17.24@43828.74,42234.25 ; U17.27@43828.74,42293.31 v1(43852.05,42293.31) ; U18.20@43828.74,43257.87 v1(43852.05,43257.87) ; U18.23@43828.74,43316.93 v1(43852.05,43316.93) 43852.05,43332.95 43848.39,43336.61 U18.24@43828.74,43336.61 ; U18.27@43828.74,43395.67 v1(43852.05,43395.67) ; v1(44726.69,39852.36) U22.28@44750,39852.36 ; v1(44726.69,39950.79) U22.23@44750,39950.79 ; v1(44726.69,40009.84) U22.20@44750,40009.84 ; v1(44726.69,40954.72) U21.28@44750,40954.72 ; v1(44726.69,41053.15) U21.23@44750,41053.15 ; v1(44726.69,42057.09) U20.28@44750,42057.09 ; v1(44726.69,42214.57) U20.20@44750,42214.57 ; v1(44726.69,43159.45) U19.28@44750,43159.45 ; U23.24@46289.37,40029.53 v1(46312.68,40029.53) ; U23.28@46289.37,40108.27 v1(46312.68,40108.27) ; U24.20@46289.37,41053.15 v1(46312.68,41053.15) ; U24.24@46289.37,41131.89 v1(46312.68,41131.89) ; U24.28@46289.37,41210.63 v1(46312.68,41210.63) ; U25.23@46289.37,42214.57 46304.26,42214.57 46312.68,42222.98 v1(46312.68,42234.25) U25.24@46289.37,42234.25 ; U25.28@46289.37,42312.99 v1(46312.68,42312.99) ; U26.20@46289.37,43257.87 v1(46312.68,43257.87) ; U26.23@46289.37,43316.93 46304.26,43316.93 46312.68,43325.34 v1(46312.68,43336.61) U26.24@46289.37,43336.61 ; U26.28@46289.37,43415.35 v1(46312.68,43415.35) ; v1(47187.32,39950.79) U30.23@47210.63,39950.79 ; v1(47187.32,40009.84) U30.20@47210.63,40009.84 ; v1(47187.32,41053.15) U29.23@47210.63,41053.15 ; v1(47187.32,42214.57) U28.20@47210.63,42214.57 ; U30.28@47210.63,39852.36 47192.64,39852.36 47187.32,39857.68 v1(47187.32,39872.05) U30.27@47210.63,39872.05 ; U29.28@47210.63,40954.72 47195.28,40954.72 47187.32,40962.68 v1(47187.32,40974.41) U29.27@47210.63,40974.41 ; U28.28@47210.63,42057.09 47197.91,42057.09 47187.32,42067.68 v1(47187.32,42076.77) U28.27@47210.63,42076.77 ; U27.28@47210.63,43159.45 v1(47187.32,43159.45) 47187.32,43172.32 47194.13,43179.13 U27.27@47210.63,43179.13 ; R21.2@48541.34,43564.96 v1(48541.34,43593.66) ; U31.24@48750,40029.53 v1@48775,40029.53 ; U31.27@48750,40088.58 48768.58,40088.58 48773.31,40093.31 v1(48773.31,40108.27) U31.28@48750,40108.27 ; U32.20@48750,41053.15 v1(48773.31,41053.15) ; U32.24@48750,41131.89 v1(48773.31,41131.89) ; U32.27@48750,41190.94 48765.94,41190.94 48773.31,41198.31 v1(48773.31,41210.63) U32.28@48750,41210.63 ; U33.23@48750,42214.57 48764.26,42214.57 48773.31,42223.61 v1(48773.31,42234.25) U33.24@48750,42234.25 ; U33.27@48750,42293.31 48764.26,42293.31 48773.31,42302.35 v1(48773.31,42312.99) U33.28@48750,42312.99 ; U34.20@48750,43257.87 v1(48773.31,43257.87) ; U34.23@48750,43316.93 48770.64,43316.93 48773.31,43319.59 v1(48773.31,43336.61) U34.24@48750,43336.61 ; U34.27@48750,43395.67 48765.67,43395.67 48773.31,43403.31 v1(48773.31,43415.35) U34.28@48750,43415.35
  Top Layer w10: C104.2@39856.3,39759.84 v1(39856.3,39792.32) U6.29@39856.3,39824.8 ; U6.14@39856.3,40135.83 v1(39856.3,40165.35) C103.2@39856.3,40200.79 ; C43.2@39856.3,40862.2 U5.29@39856.3,40927.17 ; U5.14@39856.3,41238.19 C35.2@39856.3,41301.18 ; C41.2@39856.3,41964.57 U4.29@39856.3,42029.53 ; U4.14@39856.3,42340.55 v1(39856.3,42370.08) C33.2@39856.3,42405.51 ; C99.2@39856.3,43066.93 v1(39856.3,43099.41) U3.29@39856.3,43131.89 ; U3.14@39856.3,43442.91 v1(39856.3,43472.44) C106.2@39856.3,43507.87 ; U6.43@40139.76,39852.36 v1(40169.29,39852.36) C107.2@40204.72,39852.36 ; v1(40169.29,40954.72) C40.2@40202.76,40954.72 ; v1(40169.29,42057.09) C39.2@40204.72,42057.09 ; v1(40169.29,43159.45) C105.2@40200.79,43159.45 ; C32.2@40992.13,40108.27 U7.43@41057.09,40108.27 ; C34.2@40992.13,41210.63 U8.43@41057.09,41210.63 ; C38.2@40992.13,42312.99 U9.43@41057.09,42312.99 ; C98.2@40992.13,43415.35 U10.43@41057.09,43415.35 ; C36.2@41340.55,39759.84 v1(41340.55,39795.28) U7.14@41340.55,39824.8 ; U7.29@41340.55,40135.83 C102.2@41340.55,40200.79 ; C37.2@41340.55,40862.2 U8.14@41340.55,40927.17 ; U8.29@41340.55,41238.19 C101.2@41340.55,41303.15 ; C96.2@41340.55,41964.57 U9.14@41340.55,42029.53 ; U9.29@41340.55,42340.55 C100.2@41340.55,42405.51 ; C97.2@41340.55,43066.93 U10.14@41340.55,43131.89 ; U10.29@41340.55,43442.91 C42.2@41340.55,43507.87 ; C236.2@42316.93,39759.84 v1(42316.93,39795) U14.29@42316.93,39824.8 ; U14.14@42316.93,40135.83 v1(42316.93,40168.31) C235.2@42316.93,40200.79 ; C175.2@42316.93,40862.2 v1(42316.93,40900) U13.29@42316.93,40927.17 ; U13.14@42316.93,41238.19 v1(42316.93,41269.69) C167.2@42316.93,41301.18 ; C173.2@42316.93,41964.57 v1(42316.93,42000) U12.29@42316.93,42029.53 ; U12.14@42316.93,42340.55 v1(42316.93,42370) C165.2@42316.93,42405.51 ; C231.2@42317.01,43067.48 v1(42317.01,43099.96) U11.29@42317.01,43132.44 ; U11.14@42317.01,43443.46 v1(42317.01,43472.99) C238.2@42317.01,43508.43 ; U14.43@42600.39,39852.36 v1(42630,39852.36) C239.2@42665.35,39852.36 ; U13.43@42600.39,40954.72 C172.2@42663.39,40954.72 ; v1@42629.45,43159.45 C237.2@42661.42,43159.45 ; v1(42630,42057.09) C171.2@42665.35,42057.09 ; C166.2@43452.76,41210.63 U16.43@43517.72,41210.63 ; C170.2@43452.76,42312.99 U17.43@43517.72,42312.99 ; C230.2@43452.76,43415.35 U18.43@43517.72,43415.35 ; v1(43488.19,40108.27) U15.43@43517.72,40108.27 ; v1(43801.18,39795.28) U15.14@43801.18,39824.8 ; U15.29@43801.18,40135.83 C234.2@43801.18,40200.79 ; C169.2@43801.18,40862.2 U16.14@43801.18,40927.17 ; U16.29@43801.18,41238.19 C233.2@43801.18,41303.15 ; C228.2@43801.18,41964.57 U17.14@43801.18,42029.53 ; U17.29@43801.18,42340.55 C232.2@43801.18,42405.51 ; C229.2@43801.18,43066.93 U18.14@43801.18,43131.89 ; U18.29@43801.18,43442.91 C174.2@43801.18,43507.87 ; C368.2@44777.56,39759.84 v1(44777.56,39792.32) U22.29@44777.56,39824.8 ; U22.14@44777.56,40135.83 v1(44777.56,40165.35) C367.2@44777.56,40200.79 ; C307.2@44777.56,40860.24 v1(44777.56,40892.72) U21.29@44777.56,40925.2 ; U21.14@44777.56,41236.22 v1(44777.56,41265.75) C299.2@44777.56,41301.18 ; C305.2@44777.56,41964.57 v1(44777.56,41997.05) U20.29@44777.56,42029.53 ; U20.14@44777.56,42340.55 v1(44777.56,42370.08) C297.2@44777.56,42405.51 ; C363.2@44777.56,43066.93 v1(44777.56,43099.41) U19.29@44777.56,43131.89 ; U19.14@44777.56,43442.91 v1(44777.56,43472.44) C370.2@44777.56,43507.87 ; U22.43@45061.02,39852.36 C371.2@45122.05,39852.36 ; U21.43@45061.02,40952.76 C304.2@45122.05,40952.76 ; U20.43@45061.02,42057.09 C303.2@45122.05,42057.09 ; U19.43@45061.02,43159.45 C369.2@45122.05,43159.45 ; C296.2@45913.39,40108.27 U23.43@45978.35,40108.27 ; C298.2@45913.39,41210.63 U24.43@45978.35,41210.63 ; C302.2@45913.39,42312.99 U25.43@45978.35,42312.99 ; C362.2@45913.39,43415.35 U26.43@45978.35,43415.35 ; C300.2@46261.81,39759.84 v1(46261.81,39795.28) U23.14@46261.81,39824.8 ; U23.29@46261.81,40135.83 C366.2@46261.81,40200.79 ; C301.2@46261.81,40862.2 U24.14@46261.81,40927.17 ; U24.29@46261.81,41238.19 C365.2@46261.81,41303.15 ; C360.2@46261.81,41964.57 U25.14@46261.81,42029.53 ; U25.29@46261.81,42340.55 C364.2@46261.81,42405.51 ; C361.2@46261.81,43066.93 U26.14@46261.81,43131.89 ; U26.29@46261.81,43442.91 C306.2@46261.81,43507.87 ; C500.2@47238.19,39759.84 U30.29@47238.19,39824.8 ; U30.14@47238.19,40135.83 v1(47238.19,40165.35) C499.2@47238.19,40200.79 ; C439.2@47238.19,40860.24 v1(47238.19,40892.72) U29.29@47238.19,40925.2 ; U29.14@47238.19,41236.22 v1(47238.19,41265.75) C431.2@47238.19,41301.18 ; C437.2@47238.19,41964.57 v1(47238.19,41997.05) U28.29@47238.19,42029.53 ; U28.14@47238.19,42340.55 v1(47238.19,42370.08) C429.2@47238.19,42405.51 ; C495.2@47238.19,43066.93 v1(47238.19,43099.41) U27.29@47238.19,43131.89 ; U27.14@47238.19,43442.91 v1(47238.19,43472.44) C502.2@47238.19,43507.87 ; U30.43@47521.65,39852.36 C503.2@47582.68,39852.36 ; U29.43@47521.65,40954.72 C436.2@47582.68,40954.72 ; U28.43@47521.65,42057.09 C435.2@47582.68,42057.09 ; U27.43@47521.65,43159.45 C501.2@47582.68,43159.45 ; C428.2@48374.02,40108.27 U31.43@48438.98,40108.27 ; C430.2@48374.02,41210.63 U32.43@48438.98,41210.63 ; C434.2@48374.02,42312.99 U33.43@48438.98,42312.99 ; C494.2@48374.02,43415.35 U34.43@48438.98,43415.35 ; C432.2@48722.44,39759.84 v1(48722.44,39795.28) U31.14@48722.44,39824.8 ; U31.29@48722.44,40135.83 C498.2@48722.44,40200.79 ; C433.2@48722.44,40862.2 U32.14@48722.44,40927.17 ; U32.29@48722.44,41238.19 C497.2@48722.44,41303.15 ; C492.2@48722.44,41964.57 U33.14@48722.44,42029.53 ; U33.29@48722.44,42340.55 C496.2@48722.44,42405.51 ; C493.2@48722.44,43066.93 U34.14@48722.44,43131.89 ; U34.29@48722.44,43442.91 C438.2@48722.44,43507.87
  Top Layer w15: v1(39735,43724.41) R18.2@39761.81,43724.41 ; R74.2@44365,41854.53 v1(44365,41880)
  Top Layer w20: R15.1@40520,43610.47 v1(40550.47,43610.47) ; v3(42475.47,44835.47) R71.1@42475.47,44915 ; C601.1@44365,41410 v6(44365,41460.39) U42.8@44365,41512.48
  Top Layer w25: U2.3@40592.52,43726.38 40592.52,43687.01 40600.39,43679.13 40667.32,43679.13 ; U2.1@40667.32,43726.38 40667.32,43679.13 ; C14.2@40744.09,43683.07 C15.2@40744.09,43631.89 v1(40700,43631.89) U2.6@40667.32,43631.89 40667.32,43679.13 ; U36.3@43053.15,43726.38 43053.15,43687.01 43061.02,43679.13 43127.95,43679.13 ; U36.1@43127.95,43726.38 43127.95,43679.13 ; C561.2@43204.72,43683.07 C562.2@43204.72,43631.89 v1(43160,43631.89) U36.6@43127.95,43631.89 43127.95,43679.13 ; U38.3@45513.78,43726.38 45513.78,43687.01 45521.65,43679.13 45588.58,43679.13 ; U38.1@45588.58,43726.38 45588.58,43679.13 ; C577.2@45665.35,43683.07 C578.2@45665.35,43631.89 v1(45620,43631.89) U38.6@45588.58,43631.89 45588.58,43679.13 ; U40.3@47974.41,43726.38 47974.41,43687.01 47982.28,43679.13 48049.21,43679.13 ; U40.1@48049.21,43726.38 48049.21,43679.13 ; C593.2@48125.98,43683.07 C594.2@48125.98,43631.89 v1(48080,43631.89) U40.6@48049.21,43631.89 48049.21,43679.13
  Top Layer w50: POWER.3@41404.37,45130 POWER.4@41483.11,45130 41645.2,44967.91 41710,44967.91 L5.2@41865,44967.91 ; v1(44180,42945) C602.2@44235,42945
  Mid-Layer 1 w50: v3(41795,44967.91) 41927.91,44835 42560,44835 42740,44655 42740,44480 42970,44250 43545,44250 43660,44135 43660,43865 44042.91,43482.09 44042.91,43082.09 v1(44180,42945)
  Mid-Layer 2 w9: 48541.34,43433.07 v1(48541.34,43593.66)
  Mid-Layer 2 w15: v1(39735,43724.41) 39735,43615 39856.3,43493.7 v1(39856.3,43472.44) ; v6(44365,41460.39) 44365,41515 44415,41565 44415,41830 v1(44365,41880)
  Mid-Layer 2 w25: 39856.3,42040 40152.2,42040 v1(40169.29,42057.09) ; v1(39856.3,43472.44) 39818.9,43435.04 39818.9,43179.13 39856.3,43141.73 ; v1(40169.29,40954.72) 40151.57,40937.01 39856.3,40937.01 ; v1(40169.29,43159.45) 40151.57,43141.73 39856.3,43141.73 ; v1(40550.47,43610.47) 40571.89,43631.89 40773.11,43631.89 40989.65,43415.35 v1(41027.56,43415.35) 41045.28,43433.07 41340.55,43433.07 ; v1(41027.56,40108.27) 41045.28,40125.98 41340.55,40125.98 ; v1(41027.56,41210.63) 41045.28,41228.35 41340.55,41228.35 ; v1(41027.56,42312.99) 41045.28,42330.71 41340.55,42330.71 ; v1(41340.55,39795.28) 41300.83,39835 41000,39835 40980,39855 40465,39855 40425,39895 40211.93,39895 v1(40169.29,39852.36) 40151.93,39835 39920,39835 39877.32,39792.32 v1(39856.3,39792.32) 39805.43,39843.19 39805.43,40114.49 v1(39856.3,40165.35) 39856.3,40214.57 39818.9,40251.97 39818.9,40857.28 v1(39856.3,40894.69) 39856.3,40937.01 ; v1(41340.55,43475.39) 41340.55,43433.07 ; v1@41340.83,39795 v1(42316.93,39795) 42340,39795 42390,39845 42530,39845 42550,39825 42602.64,39825 v1(42630,39852.36) 42672.64,39895 42795,39895 42835,39855 43410,39855 43488.19,39933.19 v1(43488.19,40108.27) 43505.91,40125.98 43735.98,40125.98 43778.31,40168.31 v1(43801.18,40168.31) ; 41391.42,39795 41391.42,40075.12 41340.55,40125.98 ; 42266.06,39795 42266.06,40117.44 v1(42316.93,40168.31) 42316.93,40208.07 42265,40260 42265,40790 42316.93,40841.93 v1(42316.93,40900) ; v1(42317.01,43472.99) 42265,43420.98 42265,43151.97 v1(42317.01,43099.96) ; v1(42630,40954.72) 42610.28,40935 42385,40935 42350,40900 v1(42316.93,40900) ; v1(42630,42057.09) 42617.91,42045 42395,42045 42350,42000 v1(42316.93,42000) ; v1(42630,43160) 42612.28,43142.28 42382.28,43142.28 42339.96,43099.96 v1(42317.01,43099.96) ; v1(43160,43631.89) 43233.11,43631.89 43449.65,43415.35 v1(43488.19,43415.35) 43505.91,43433.07 43738.07,43433.07 43780.39,43475.39 v1(43801.18,43475.39) 43852.05,43424.53 v1(43852.05,43316.93) 43852.05,43153.23 v1(43801.18,43102.36) 43801.18,43053.15 43838.58,43015.75 43838.58,42410.43 v1(43801.18,42373.03) 43801.18,42344.17 ; v1(43488.19,41210.63) 43505.91,41228.35 43738.35,41228.35 43780.67,41270.67 v1(43801.18,41270.67) ; v1(43488.19,42312.99) 43505.91,42330.71 43814.65,42330.71 v1(43852.05,42293.31) v1(43852.05,42214.57) 43852.05,42050.87 v1(43801.18,42000) 43801.18,41950.79 43838.58,41913.39 43838.58,41348.58 43801.18,41311.18 v1(43801.18,41270.67) ; v1(43801.18,39795.28) 43852.05,39846.14 43852.05,40117.44 v1(43801.18,40168.31) ; 43840,42945 v1(44180,42945) 44740,42945 ; v6(44365,41460.39) 44740,41460.39 ; v1@44777.56,40163.39 44777.56,40212.6 44740.16,40250 44740.16,40820.16 44777.56,40857.56 v1(44777.56,40892.72) ; v1(44777.56,40165.35) 44726.69,40114.49 44726.69,39843.19 v1(44777.56,39792.32) 44792.32,39792.32 44834.65,39834.65 45072.83,39834.65 v1(45090.55,39852.36) 45133.19,39895 45465,39895 45500,39860 45855,39860 45885,39830 46195,39830 46229.72,39795.28 v1(46261.81,39795.28) 47238.19,39795.28 47277.56,39834.65 47533.46,39834.65 v1(47551.18,39852.36) 47593.82,39895 47910,39895 47950,39855 48430,39855 48450,39835 48655,39835 48694.72,39795.28 v1(48722.44,39795.28) 48773.31,39846.14 v1(48773.31,40108.27) 48773.31,40117.44 v1(48722.44,40168.31) ; v1(44777.56,41265.75) 44726.69,41214.88 44726.69,40943.58 v1(44777.56,40892.72) ; v1@44777.56,41267.72 44777.56,41316.93 44740.16,41354.33 44740.16,41925.16 44777.56,41962.56 v1(44777.56,41997.05) ; v1(44777.56,43472.44) 44726.69,43421.57 v1(44726.69,43159.45) 44726.69,43150.28 v1(44777.56,43099.41) ; v1(45090.55,40952.76) 45072.83,40935.04 44845.04,40935.04 44802.72,40892.72 v1(44777.56,40892.72) ; v1(45090.55,42057.09) 45072.83,42039.37 44846.56,42039.37 44804.23,41997.05 v1(44777.56,41997.05) ; v1(45090.55,43159.45) 45072.83,43141.73 44846.56,43141.73 44804.23,43099.41 v1(44777.56,43099.41) ; v1(45620,43631.89) 45688.11,43631.89 45904.65,43415.35 v1(45948.82,43415.35) 45966.54,43433.07 46198.07,43433.07 46240.39,43475.39 v1(46261.81,43475.39) 46279.61,43475.39 46312.68,43442.32 v1(46312.68,43415.35) v1(46312.68,43336.61) v1(46312.68,43257.87) 46312.68,43153.23 v1(46261.81,43102.36) 46261.81,43053.15 46299.21,43015.75 46299.21,42454.21 46261.81,42416.81 v1(46261.81,42373.03) ; v1(45948.82,40108.27) 45966.54,40125.98 46192.81,40125.98 46235.14,40168.31 v1(46261.81,40168.31) ; v1(45948.82,41210.63) 45966.54,41228.35 46192.81,41228.35 46235.14,41270.67 v1(46261.81,41270.67) ; v1(45948.82,42312.99) 45966.54,42330.71 46192.81,42330.71 46235.14,42373.03 v1(46261.81,42373.03) ; 46312.68,39795.28 46312.68,40117.44 v1(46261.81,40168.31) ; 47187.32,39795.28 v1(47187.32,39872.05) v1(47187.32,39950.79) v1(47187.32,40009.84) 47187.32,40114.49 v1(47238.19,40165.35) ; v1@47187.32,43150.28 v1(47238.19,43099.41) ; v1(47187.32,43159.45) 47187.32,43421.57 v1(47238.19,43472.44) ; v1@47238.19,40163.39 47238.19,40212.6 47200.79,40250 47200.79,40810.79 47238.19,40848.19 v1(47238.19,40892.72) ; v1(47238.19,41265.75) 47187.32,41214.88 v1(47187.32,40974.41) 47187.32,40943.58 v1(47238.19,40892.72) ; v1@47238.19,41267.72 47238.19,41316.93 47200.79,41354.33 47200.79,41920.79 47238.19,41958.19 v1(47238.19,41997.05) ; v1(47551.18,40952.76) 47533.46,40935.04 47307.19,40935.04 47264.86,40892.72 v1(47238.19,40892.72) ; v1(47551.18,42057.09) 47533.46,42039.37 47307.19,42039.37 47264.86,41997.05 v1(47238.19,41997.05) ; v1(47551.18,43159.45) 47533.46,43141.73 47307.19,43141.73 47264.86,43099.41 v1(47238.19,43099.41) ; v1(48080,43631.89) 48148.82,43631.89 48365.35,43415.35 v1(48409.45,43415.35) 48427.17,43433.07 48541.34,43433.07 48618.07,43433.07 48660.39,43475.39 v1(48722.44,43475.39) 48773.31,43424.53 v1(48773.31,43415.35) v1(48773.31,43336.61) 48773.31,43153.23 v1(48722.44,43102.36) 48722.44,43053.15 48759.84,43015.75 48759.84,42459.84 48722.44,42422.44 v1(48722.44,42373.03) ; v1(48409.45,40108.27) 48427.17,40125.98 48650.98,40125.98 48693.31,40168.31 v1(48722.44,40168.31) ; v1(48409.45,41210.63) 48427.17,41228.35 48653.44,41228.35 48695.77,41270.67 v1(48722.44,41270.67) ; v1(48409.45,42312.99) 48427.17,42330.71 48653.44,42330.71 48695.77,42373.03 v1(48722.44,42373.03) ; 39856.3,40937.01 39805.43,40987.87 39805.43,41216.85 v1(39856.3,41267.72) 39856.3,41316.93 39818.9,41354.33 39818.9,41959.65 v1(39856.3,41997.05) 39856.3,42039.37 39805.43,42090.24 39805.43,42319.21 v1(39856.3,42370.08) 39856.3,42419.29 39818.9,42456.69 39818.9,43062.01 v1(39856.3,43099.41) 39856.3,43141.73 ; 41340.55,40125.98 v1(41340.55,40168.31) 41377.95,40205.71 41377.95,40811.02 41340.55,40848.43 v1(41340.55,40897.64) 41391.42,40948.5 41391.42,41177.48 41340.55,41228.35 ; 41340.55,41228.35 v1(41340.55,41270.67) 41377.95,41308.07 41377.95,41913.39 41340.55,41950.79 v1(41340.55,42000) 41391.42,42050.87 v1(41391.42,42225) 41391.42,42279.84 41340.55,42330.71 ; 41340.55,42330.71 v1(41340.55,42373.03) 41377.95,42410.43 41377.95,43015.75 41340.55,43053.15 v1(41340.55,43102.36) 41391.42,43153.23 v1(41391.42,43257.87) v1(41391.42,43336.61) 41391.42,43382.2 41340.55,43433.07 ; v1(42316.93,40900) 42266.06,40950.87 42266.06,41218.82 v1(42316.93,41269.69) 42316.93,41323.07 42270,41370 42270,41890 42316.93,41936.93 v1(42316.93,42000) ; v1(42316.93,42000) 42266.06,42050.87 42266.06,42319.13 v1(42316.93,42370) 42316.93,42428.07 42275,42470 42275,43015 42317.01,43057.01 v1(42317.01,43099.96) ; v1(43801.18,40168.31) 43838.58,40205.71 43838.58,40811.02 43801.18,40848.43 v1(43801.18,40897.64) 43852.05,40948.5 43852.05,41219.8 v1(43801.18,41270.67) ; v1(44777.56,41997.05) 44726.69,42047.91 44726.69,42319.21 v1(44777.56,42370.08) 44777.56,42419.29 44740.16,42456.69 44740.16,43005.16 44777.56,43042.56 v1(44777.56,43099.41) ; v1(46261.81,40168.31) 46261.81,40221.81 46299.21,40259.21 46299.21,40811.02 46261.81,40848.43 v1(46261.81,40897.64) 46312.68,40948.5 46312.68,41219.8 v1(46261.81,41270.67) ; v1(46261.81,41270.67) 46261.81,41326.81 46299.21,41364.21 46299.21,41913.39 46261.81,41950.79 v1(46261.81,42000) 46312.68,42050.87 v1(46312.68,42234.25) v1(46312.68,42312.99) 46312.68,42322.17 v1(46261.81,42373.03) ; v1(47238.19,41997.05) 47187.32,42047.91 v1(47187.32,42076.77) 47187.32,42319.21 v1(47238.19,42370.08) 47238.19,42419.29 47200.79,42456.69 47200.79,43025.79 47238.19,43063.19 v1(47238.19,43099.41) ; v1(48722.44,40168.31) 48722.44,40227.44 48759.84,40264.84 48759.84,40811.02 48722.44,40848.43 v1(48722.44,40897.64) 48773.31,40948.5 v1(48773.31,41053.15) v1(48773.31,41131.89) v1(48773.31,41210.63) 48773.31,41219.8 v1(48722.44,41270.67) ; v1(48722.44,41270.67) 48722.44,41317.44 48759.84,41354.84 48759.84,41913.39 48722.44,41950.79 v1(48722.44,42000) 48773.31,42050.87 v1(48773.31,42234.25) 48773.31,42322.17 v1(48722.44,42373.03)
  other v1: 47238.19,39795 48775,40030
